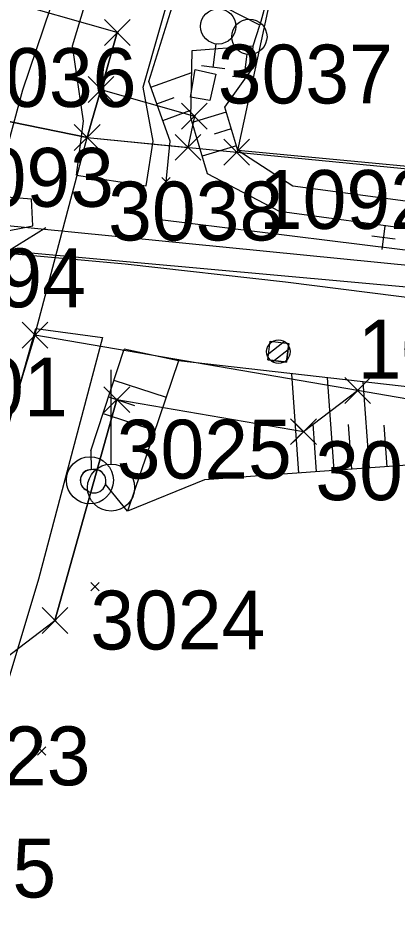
# Model space of a CAD drawing. Extents: x -738085 to -734426, y -1122197 to -1119748.
# Drawn here: x -737345.74 to -737329.62, y -1121446.65 to -1121408.62 of the extents above; entities that cross this region are included whole.
import ezdxf

# ---------------------------------------------------------------- set-up
doc = ezdxf.new("R2010")
doc.units = 0
for name, color, linetype in [('Dočasný zábor - do 1 roku', 7, 'Continuous'), ('SŽDC', 7, 'Continuous'), ('Trvalý zábor', 7, 'Continuous'), ('Vrstva 1', 7, 'Continuous'), ('Vrstva 11', 7, 'Continuous'), ('Vrstva 12', 7, 'Continuous'), ('Vrstva 16', 7, 'Continuous'), ('Vrstva 17', 7, 'Continuous'), ('Vrstva 36', 7, 'Continuous'), ('Vrstva 4', 7, 'Continuous'), ('Vrstva 41', 7, 'Continuous'), ('Vrstva 43', 7, 'Continuous'), ('Vrstva 48', 7, 'Continuous'), ('Vrstva 49', 7, 'Continuous'), ('Vrstva 51', 7, 'Continuous'), ('Vrstva 60', 7, 'Continuous'), ('Vrstva 63', 7, 'Continuous'), ('Vrstva 7', 7, 'Continuous')]:
    doc.layers.add(name, color=color, linetype=linetype)

msp = doc.modelspace()

# ---------------------------------------------------------------- linework, layer by layer
at = {"layer": 'Dočasný zábor - do 1 roku'}
for p, q in [((-737341.512, -1121409.238), (-737350.085, -1121406.783)), ((-737341.512, -1121409.238), (-737350.085, -1121406.783)), ((-737341.512, -1121409.238), (-737341.986, -1121410.894)), ((-737341.986, -1121410.894), (-737342.617, -1121413.097)), ((-737351.57, -1121411.9), (-737342.79, -1121413.7)), ((-737342.617, -1121413.097), (-737342.79, -1121413.7)), ((-737342.79, -1121413.7), (-737338.509, -1121414.118)), ((-737345.01, -1121422.1), (-737350.09, -1121438.72)), ((-737331.3, -1121424.45), (-737345.01, -1121422.1)), ((-737333.597, -1121426.194), (-737331.3, -1121424.45)), ((-737344.161, -1121434.217), (-737341.536, -1121424.835)), ((-737341.536, -1121424.835), (-737333.597, -1121426.194)), ((-737350.09, -1121438.72), (-737344.161, -1121434.217))]:
    msp.add_line(p, q, dxfattribs=at)
for points in [[(-737342.79, -1121413.7), (-737342.617, -1121413.097), (-737341.986, -1121410.894), (-737341.512, -1121409.238)], [(-737342.206, -1121411.662), (-737338.238, -1121412.791), (-737338.509, -1121414.118)], [(-737341.536, -1121424.835), (-737344.161, -1121434.217)]]:
    msp.add_lwpolyline(points, dxfattribs=at)
at = {"layer": 'SŽDC'}
for p, q in [((-737345.01, -1121422.1), (-737342.79, -1121413.7)), ((-737342.79, -1121413.7), (-737336.44, -1121414.32)), ((-737336.44, -1121414.32), (-737323.47, -1121415.6)), ((-737331.3, -1121424.45), (-737345.01, -1121422.1))]:
    msp.add_line(p, q, dxfattribs=at)
msp.add_lwpolyline([(-737320.53, -1121426.11), (-737324.57, -1121425.61), (-737331.3, -1121424.45)], dxfattribs=at)
at = {"layer": 'Trvalý zábor'}
for p, q in [((-737342.79, -1121413.7), (-737351.57, -1121411.9)), ((-737342.79, -1121413.7), (-737351.57, -1121411.9)), ((-737345.01, -1121422.1), (-737342.79, -1121413.7)), ((-737346.462, -1121426.851), (-737345.01, -1121422.1))]:
    msp.add_line(p, q, dxfattribs=at)
at = {"layer": 'Vrstva 1'}
msp.add_lwpolyline([(-737302.818, -1121423.992), (-737322.068, -1121421.435), (-737328.438, -1121420.593), (-737334.371, -1121419.848), (-737341.175, -1121419.077), (-737346.172, -1121418.626), (-737355.365, -1121418.093), (-737364.193, -1121418.049), (-737371.056, -1121418.37), (-737378.944, -1121419.134), (-737386.424, -1121420.242), (-737394.37, -1121421.821), (-737402.265, -1121423.869), (-737409.266, -1121426.074), (-737416.847, -1121428.911), (-737423.861, -1121431.965), (-737430.654, -1121435.335), (-737438.054, -1121439.528), (-737442.947, -1121442.622), (-737447.091, -1121445.439), (-737453.01, -1121449.85), (-737458.733, -1121454.549), (-737464.941, -1121460.218), (-737469.915, -1121465.238)], dxfattribs=at)
msp.add_lwpolyline([(-737302.818, -1121423.992), (-737322.068, -1121421.435), (-737328.438, -1121420.593), (-737334.371, -1121419.848), (-737341.175, -1121419.077), (-737346.172, -1121418.626), (-737355.365, -1121418.093), (-737364.193, -1121418.049), (-737371.056, -1121418.37), (-737378.944, -1121419.134), (-737386.424, -1121420.242), (-737394.37, -1121421.821), (-737402.265, -1121423.869), (-737409.266, -1121426.074), (-737416.847, -1121428.911), (-737423.861, -1121431.965), (-737430.654, -1121435.335), (-737438.054, -1121439.528), (-737442.947, -1121442.622), (-737447.091, -1121445.439), (-737453.01, -1121449.85), (-737458.733, -1121454.549), (-737464.941, -1121460.218), (-737469.915, -1121465.238)], dxfattribs=at)
at = {"layer": 'Vrstva 11'}
for p, q in [((-737334.415, -1121422.368), (-737335.14, -1121422.945)), ((-737334.187, -1121422.665), (-737334.902, -1121423.234))]:
    msp.add_line(p, q, dxfattribs=at)
msp.add_circle((-737334.666, -1121422.796), 0.5, dxfattribs=at)
at = {"layer": 'Vrstva 12'}
for p, q in [((-737335.113, -1121423.143), (-737335.013, -1121422.349)), ((-737334.319, -1121423.243), (-737334.219, -1121422.449))]:
    msp.add_line(p, q, dxfattribs=at)
for points in [[(-737338.404, -1121411.981), (-737338.197, -1121410.807), (-737337.332, -1121411.004), (-737337.585, -1121412.128), (-737338.404, -1121411.981)], [(-737335.013, -1121422.349), (-737334.219, -1121422.449), (-737334.319, -1121423.243), (-737335.113, -1121423.143), (-737335.013, -1121422.349)], [(-737335.113, -1121423.143), (-737335.113, -1121423.143), (-737334.319, -1121423.243), (-737334.319, -1121423.243)]]:
    msp.add_lwpolyline(points, dxfattribs=at)
at = {"layer": 'Vrstva 16'}
for p, q in [((-737342.62, -1121427.817), (-737342.623, -1121427.812)), ((-737342.808, -1121428.681), (-737342.808, -1121428.683))]:
    msp.add_line(p, q, dxfattribs=at)
for points in [[(-737343.24, -1121415.305), (-737342.954, -1121413.009), (-737343.417, -1121409.8), (-737341.575, -1121403.696), (-737341.249, -1121403.613), (-737341.089, -1121403.34), (-737338.309, -1121404.139)], [(-737343.24, -1121415.305), (-737340.283, -1121415.753), (-737339.986, -1121413.853), (-737340.408, -1121411.564), (-737338.309, -1121404.139)], [(-737355.255, -1121443.939), (-737352.421, -1121444.688), (-737351.819, -1121444.41), (-737351.557, -1121444.041), (-737351.044, -1121442.882), (-737350.483, -1121440.931), (-737347.779, -1121431.7), (-737344.98, -1121421.809)], [(-737344.98, -1121421.809), (-737342.138, -1121422.2), (-737344.859, -1121432.462), (-737347.782, -1121442.155), (-737348.031, -1121443.491)]]:
    msp.add_lwpolyline(points, dxfattribs=at)
for centre, major_axis, ratio, start_param, end_param in [((-737342.636, -1121428.267), (-0.305, -0.331), 0.999197, 3.852504, 6.63546), ((-737342.684, -1121428.254), (-0.076, -0.439), 0.889829, 3.182256, 6.158646), ((-737342.492, -1121428.298), (0.221, -0.446), 0.999469, 5.136573, 9.225266)]:
    msp.add_ellipse(centre, major_axis=major_axis, ratio=ratio, start_param=start_param, end_param=end_param, dxfattribs=at)
at = {"layer": 'Vrstva 17'}
for points in [[(-737336.393, -1121414.255), (-737332.639, -1121396.848), (-737330.164, -1121396.763)], [(-737220.546, -1121428.935), (-737265.552, -1121424.89), (-737285.353, -1121422.953), (-737310.199, -1121418.093), (-737323.493, -1121415.476), (-737336.393, -1121414.255)]]:
    msp.add_lwpolyline(points, dxfattribs=at)
at = {"layer": 'Vrstva 36'}
for p, q in [((-737341.778, -1121427.571), (-737341.778, -1121423.571)), ((-737341.778, -1121428.571), (-737341.778, -1121428.571))]:
    msp.add_line(p, q, dxfattribs=at)
msp.add_circle((-737341.778, -1121428.571), 1, dxfattribs=at)
at = {"layer": 'Vrstva 4'}
msp.add_line((-737348.467, -1121419.939), (-737344.544, -1121417.518), dxfattribs=at)
at = {"layer": 'Vrstva 41'}
for p, q in [((-737337.444, -1121410.723), (-737337.318, -1121409.723)), ((-737336.12, -1121411.163), (-737335.994, -1121410.163)), ((-737336.948, -1121410.786), (-737337.94, -1121410.661)), ((-737335.624, -1121411.226), (-737336.616, -1121411.101))]:
    msp.add_line(p, q, dxfattribs=at)
for centre in [(-737337.225, -1121408.979), (-737335.901, -1121409.419)]:
    msp.add_circle(centre, 0.75, dxfattribs=at)
at = {"layer": 'Vrstva 43'}
msp.add_circle((-737342.677, -1121428.263), 1, dxfattribs=at)
at = {"layer": 'Vrstva 48'}
for p, q in [((-737340.091, -1121411.564), (-737338.348, -1121410.934)), ((-737339.836, -1121412.27), (-737339.101, -1121412.004)), ((-737339.581, -1121412.975), (-737338.385, -1121412.542)), ((-737336.887, -1121412.62), (-737338.336, -1121413.058)), ((-737336.67, -1121413.338), (-737337.396, -1121413.558)), ((-737336.453, -1121414.056), (-737337.907, -1121414.496)), ((-737333.793, -1121427.955), (-737334.097, -1121423.734)), ((-737341.653, -1121424.005), (-737339.433, -1121424.732)), ((-737332.297, -1121427.847), (-737332.581, -1121423.907)), ((-737330.8, -1121427.739), (-737331.064, -1121424.08)), ((-737341.887, -1121424.718), (-737340.78, -1121425.08)), ((-737342.12, -1121425.431), (-737339.914, -1121426.153)), ((-737333.045, -1121427.901), (-737333.192, -1121425.861)), ((-737331.549, -1121427.793), (-737331.686, -1121425.893)), ((-737330.052, -1121427.685), (-737330.179, -1121425.926))]:
    msp.add_line(p, q, dxfattribs=at)
at = {"layer": 'Vrstva 49'}
for p, q in [((-737335.741, -1121409.805), (-737335.454, -1121408.93)), ((-737335.805, -1121410.82), (-737335.741, -1121409.805)), ((-737339.617, -1121415.402), (-737339.263, -1121415.756)), ((-737339.617, -1121415.756), (-737339.263, -1121415.402)), ((-737310.692, -1121420.073), (-737334.626, -1121416.845)), ((-737342.638, -1121427.011), (-737341.225, -1121422.697)), ((-737338.909, -1121423.185), (-737341.225, -1121422.697)), ((-737338.909, -1121423.185), (-737341.074, -1121429.579)), ((-737337.814, -1121428.245), (-737341.074, -1121429.579)), ((-737341.074, -1121429.579), (-737342.011, -1121428.426)), ((-737342.636, -1121432.597), (-737342.282, -1121432.951)), ((-737342.636, -1121432.951), (-737342.282, -1121432.597)), ((-737344.91, -1121439.59), (-737344.556, -1121439.944)), ((-737344.91, -1121439.944), (-737344.556, -1121439.59))]:
    msp.add_line(p, q, dxfattribs=at)
for points in [[(-737339.798, -1121417.177), (-737339.44, -1121415.579), (-737339.261, -1121413.861), (-737340.178, -1121411.324), (-737338.542, -1121406.093), (-737337.83, -1121406.218)], [(-737335.143, -1121407.767), (-737335.454, -1121408.93), (-737336.934, -1121408.171)], [(-737334.626, -1121416.845), (-737337.683, -1121415.248), (-737338.392, -1121412.87), (-737338.327, -1121410.002)], [(-737338.327, -1121410.002), (-737335.741, -1121409.805)], [(-737334.06, -1121415.764), (-737336.393, -1121414.255), (-737336.95, -1121412.412), (-737335.805, -1121410.82)], [(-737285.353, -1121422.953), (-737310.199, -1121418.093), (-737316.732, -1121418.077), (-737334.06, -1121415.764)], [(-737308.871, -1121421.248), (-737310.948, -1121421.309), (-737321.028, -1121419.555), (-737322.413, -1121419.333), (-737339.798, -1121417.177)], [(-737310.424, -1121426.453), (-737322.355, -1121425.073), (-737338.909, -1121423.185)], [(-737342.638, -1121427.011), (-737342.623, -1121427.812), (-737342.62, -1121427.817)], [(-737310.615, -1121428.097), (-737322.711, -1121427.156), (-737337.814, -1121428.245)]]:
    msp.add_lwpolyline(points, dxfattribs=at)
msp.add_ellipse((-737342.492, -1121428.298), major_axis=(-0.221, 0.446), ratio=0.999469, start_param=3.994162, end_param=6.083673, dxfattribs=at)
at = {"layer": 'Vrstva 51'}
msp.add_lwpolyline([(-737353.168, -1121417.366), (-737346.611, -1121417.744), (-737345.104, -1121417.446), (-737345.158, -1121416.325), (-737346.753, -1121416.185), (-737345.527, -1121411.676), (-737341.982, -1121401.209), (-737339.828, -1121398.495), (-737336.179, -1121397.868)], dxfattribs=at)
at = {"layer": 'Vrstva 60'}
for p, q in [((-737341.062, -1121409.688), (-737342.062, -1121408.688)), ((-737341.062, -1121408.788), (-737342.062, -1121409.788)), ((-737341.962, -1121409.688), (-737340.962, -1121408.688)), ((-737341.962, -1121408.788), (-737340.962, -1121409.788)), ((-737341.512, -1121409.238), (-737341.512, -1121409.238)), ((-737341.756, -1121412.112), (-737342.756, -1121411.112)), ((-737342.656, -1121412.112), (-737341.656, -1121411.112)), ((-737341.756, -1121411.212), (-737342.756, -1121412.212)), ((-737342.656, -1121411.212), (-737341.656, -1121412.212)), ((-737342.206, -1121411.662), (-737342.206, -1121411.662)), ((-737337.788, -1121413.241), (-737338.788, -1121412.241)), ((-737338.688, -1121413.241), (-737337.688, -1121412.241)), ((-737337.788, -1121412.341), (-737338.788, -1121413.341)), ((-737338.688, -1121412.341), (-737337.688, -1121413.341)), ((-737338.238, -1121412.791), (-737338.238, -1121412.791)), ((-737342.34, -1121414.15), (-737343.34, -1121413.15)), ((-737342.34, -1121413.25), (-737343.34, -1121414.25)), ((-737343.24, -1121414.15), (-737342.24, -1121413.15)), ((-737343.24, -1121413.25), (-737342.24, -1121414.25)), ((-737342.79, -1121413.7), (-737342.79, -1121413.7)), ((-737338.059, -1121414.568), (-737339.059, -1121413.568)), ((-737338.059, -1121413.668), (-737339.059, -1121414.668)), ((-737338.959, -1121414.568), (-737337.959, -1121413.568)), ((-737338.959, -1121413.668), (-737337.959, -1121414.668)), ((-737335.99, -1121414.77), (-737336.99, -1121413.77)), ((-737336.89, -1121414.77), (-737335.89, -1121413.77)), ((-737338.509, -1121414.118), (-737338.509, -1121414.118)), ((-737335.99, -1121413.87), (-737336.99, -1121414.87)), ((-737336.89, -1121413.87), (-737335.89, -1121414.87)), ((-737336.44, -1121414.32), (-737336.44, -1121414.32)), ((-737344.56, -1121422.55), (-737345.56, -1121421.55)), ((-737344.56, -1121421.65), (-737345.56, -1121422.65)), ((-737345.46, -1121422.55), (-737344.46, -1121421.55)), ((-737345.46, -1121421.65), (-737344.46, -1121422.65)), ((-737345.01, -1121422.1), (-737345.01, -1121422.1)), ((-737330.85, -1121424.9), (-737331.85, -1121423.9)), ((-737330.85, -1121424), (-737331.85, -1121425)), ((-737331.75, -1121424.9), (-737330.75, -1121423.9)), ((-737331.75, -1121424), (-737330.75, -1121425)), ((-737341.086, -1121425.285), (-737342.086, -1121424.285)), ((-737341.086, -1121424.385), (-737342.086, -1121425.385)), ((-737341.986, -1121425.285), (-737340.986, -1121424.285)), ((-737341.986, -1121424.385), (-737340.986, -1121425.385)), ((-737331.3, -1121424.45), (-737331.3, -1121424.45)), ((-737341.536, -1121424.835), (-737341.536, -1121424.835)), ((-737333.147, -1121426.644), (-737334.147, -1121425.644)), ((-737333.147, -1121425.744), (-737334.147, -1121426.744)), ((-737334.047, -1121426.644), (-737333.047, -1121425.644)), ((-737334.047, -1121425.744), (-737333.047, -1121426.744)), ((-737333.597, -1121426.194), (-737333.597, -1121426.194)), ((-737343.711, -1121434.667), (-737344.711, -1121433.667)), ((-737343.711, -1121433.767), (-737344.711, -1121434.767)), ((-737344.611, -1121434.667), (-737343.611, -1121433.667)), ((-737344.611, -1121433.767), (-737343.611, -1121434.767)), ((-737344.161, -1121434.217), (-737344.161, -1121434.217))]:
    msp.add_line(p, q, dxfattribs=at)
at = {"layer": 'Vrstva 63'}
for p in [(-737364.617, -1121415.627), (-737376.128, -1121415.817)]:
    msp.add_line(p, (-737220.606, -1121429.814), dxfattribs=at)
at = {"layer": 'Vrstva 7'}
for p, q in [((-737330.258, -1121418.456), (-737330.134, -1121417.464)), ((-737329.7, -1121418.022), (-737330.692, -1121417.898))]:
    msp.add_line(p, q, dxfattribs=at)

# ---------------------------------------------------------------- texts
at = {"layer": 'Vrstva 60'}
for s, p in [('3036', (-737348.135, -1121412.401)), ('3037', (-737337.243, -1121412.254)), ('1093', (-737349.095, -1121416.643)), ('1092', (-737335.497, -1121417.581)), ('3038', (-737341.902, -1121418.073)), ('1094', (-737350.283, -1121420.914)), ('1095', (-737331.3, -1121423.942)), ('2001', (-737351.058, -1121425.548)), ('3025', (-737341.536, -1121428.19)), ('3026', (-737333.096, -1121429.106)), ('3024', (-737342.659, -1121435.449)), ('3023', (-737350.09, -1121441.22)), ('3005', (-737351.547, -1121445.987))]:
    msp.add_text(s, height=2.5, dxfattribs=at).set_placement(p)

doc.saveas('drawing.dxf')
